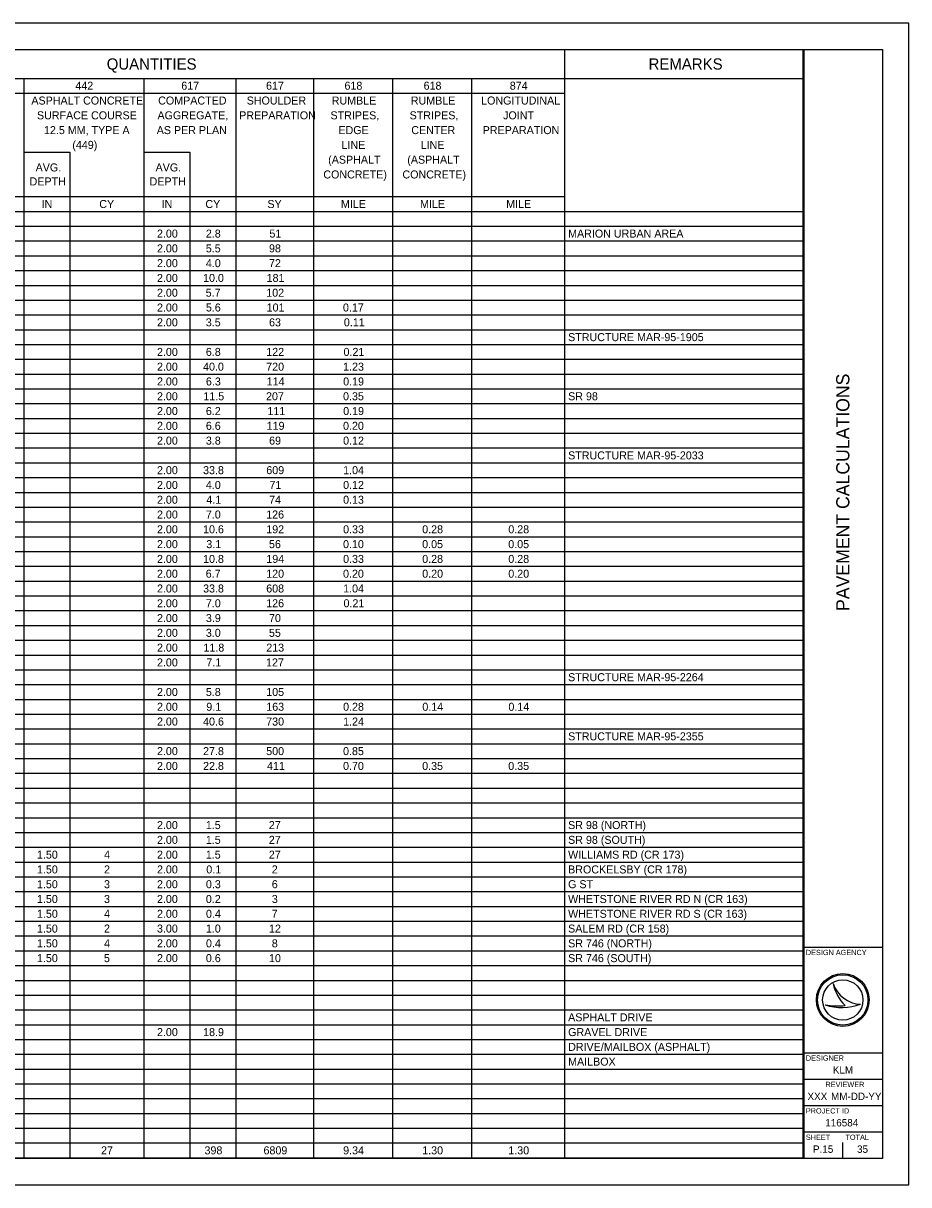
# Model space of a CAD drawing. Extents: x 0 to 34, y 0 to 22.
# Drawn here: x 17.22 to 34, y 0 to 22 of the extents above; entities that cross this region are included whole.
import ezdxf

# ---------------------------------------------------------------- set-up
doc = ezdxf.new("R2010")
doc.units = 0
for name, color, linetype in [('SH_Border', 7, 'Continuous'), ('SH_Cut_Line', 7, 'Continuous'), ('SH_Data', 7, 'Continuous'), ('SH_Text', 7, 'Continuous')]:
    doc.layers.add(name, color=color, linetype=linetype)

msp = doc.modelspace()

# ---------------------------------------------------------------- linework, layer by layer
at = {"layer": 'SH_Border'}
for p, q in [((32, 0.5), (32, 21.5)), ((32, 4.5), (33.5, 4.5)), ((32, 2.5), (33.5, 2.5)), ((32, 2), (33.5, 2)), ((32, 1.5), (33.5, 1.5)), ((32, 1), (33.5, 1))]:
    msp.add_line(p, q, dxfattribs=at)
msp.add_lwpolyline([(1.5, 21.5), (33.5, 21.5), (33.5, 0.5), (1.5, 0.5)], close=True, dxfattribs=at)
at = {"layer": 'SH_Cut_Line'}
msp.add_lwpolyline([(0, 0), (34, 0), (34, 22), (0, 22)], close=True, dxfattribs=at)
at = {"layer": 'SH_Data'}
for p, q in [((32.567, 3.81), (32.567, 3.81)), ((32.417, 3.41), (32.417, 3.41)), ((32.75, 3.5), (32.75, 3.5)), ((33.087, 3.419), (33.087, 3.419)), ((32.375, 0.675), (32.375, 0.675)), ((32.75, 0.5), (32.75, 0.8))]:
    msp.add_line(p, q, dxfattribs=at)
for radius in [0.5, 0.477, 0.477, 0.382]:
    msp.add_circle((32.75, 3.5), radius, dxfattribs=at)
for centre, radius, start, end in [((33.116, 3.998), 0.58, 198.9257, 198.9319), ((33.347, 3.97), 0.796, 191.6379, 191.6421), ((33.116, 3.998), 0.58, 198.9319, 267.1657), ((33.347, 3.97), 0.796, 191.6421, 226.0947), ((32.739, 4.37), 1.013, 251.4576, 290.0832), ((32.648, 4.654), 1.266, 259.4964, 259.4995), ((32.739, 4.37), 1.013, 251.4527, 251.4576), ((32.648, 4.654), 1.266, 259.4995, 276.6672)]:
    msp.add_arc(centre, radius, start, end, dxfattribs=at)
at = {"layer": 'SH_Text'}
for p, q in [((1.5, 21.5), (32.011, 21.5)), ((27.48, 21.5), (27.48, 0.512)), ((32.011, 21.5), (32.011, 0.512)), ((1.5, 20.956), (32.011, 20.956)), ((17.233, 20.956), (17.233, 0.512)), ((19.507, 20.956), (19.507, 0.512)), ((21.253, 20.956), (21.253, 0.512)), ((22.719, 20.956), (22.719, 0.512)), ((24.218, 20.956), (24.218, 0.512)), ((25.717, 20.956), (25.717, 0.512)), ((11.747, 20.676), (27.48, 20.676)), ((17.233, 19.556), (18.106, 19.556)), ((18.106, 19.556), (18.106, 0.512)), ((19.507, 19.556), (20.38, 19.556)), ((20.38, 19.556), (20.38, 0.512)), ((9.638, 18.716), (27.48, 18.716)), ((1.5, 18.436), (32.011, 18.436)), ((1.5, 18.156), (32.011, 18.156)), ((1.5, 17.876), (32.011, 17.876)), ((1.5, 17.596), (32.011, 17.596)), ((1.5, 17.315), (32.011, 17.315)), ((1.5, 17.035), (32.011, 17.035)), ((1.5, 16.755), (32.011, 16.755)), ((1.5, 16.475), (32.011, 16.475)), ((1.5, 16.195), (32.011, 16.195)), ((1.5, 15.915), (32.011, 15.915)), ((1.5, 15.635), (32.011, 15.635)), ((1.5, 15.355), (32.011, 15.355)), ((1.5, 15.075), (32.011, 15.075)), ((1.5, 14.795), (32.011, 14.795)), ((1.5, 14.515), (32.011, 14.515)), ((1.5, 14.235), (32.011, 14.235)), ((1.5, 13.955), (32.011, 13.955)), ((1.5, 13.675), (32.011, 13.675)), ((1.5, 13.395), (32.011, 13.395)), ((1.5, 13.114), (32.011, 13.114)), ((1.5, 12.834), (32.011, 12.834)), ((1.5, 12.554), (32.011, 12.554)), ((1.5, 12.274), (32.011, 12.274)), ((1.5, 11.994), (32.011, 11.994)), ((1.5, 11.714), (32.011, 11.714)), ((1.5, 11.434), (32.011, 11.434)), ((1.5, 11.154), (32.011, 11.154)), ((1.5, 10.874), (32.011, 10.874)), ((1.5, 10.594), (32.011, 10.594)), ((1.5, 10.314), (32.011, 10.314)), ((1.5, 10.034), (32.011, 10.034)), ((1.5, 9.754), (32.011, 9.754)), ((1.5, 9.474), (32.011, 9.474)), ((1.5, 9.194), (32.011, 9.194)), ((1.5, 8.914), (32.011, 8.914)), ((1.5, 8.633), (32.011, 8.633)), ((1.5, 8.353), (32.011, 8.353)), ((1.5, 8.073), (32.011, 8.073)), ((1.5, 7.793), (32.011, 7.793)), ((1.5, 7.513), (32.011, 7.513)), ((1.5, 7.233), (32.011, 7.233)), ((1.5, 6.953), (32.011, 6.953)), ((1.5, 6.673), (32.011, 6.673)), ((1.5, 6.393), (32.011, 6.393)), ((1.5, 6.113), (32.011, 6.113)), ((1.5, 5.833), (32.011, 5.833)), ((1.5, 5.553), (32.011, 5.553)), ((1.5, 5.273), (32.011, 5.273)), ((1.5, 4.993), (32.011, 4.993)), ((1.5, 4.713), (32.011, 4.713)), ((1.5, 4.432), (32.011, 4.432)), ((1.5, 4.152), (32.011, 4.152)), ((1.5, 3.872), (32.011, 3.872)), ((1.5, 3.592), (32.011, 3.592)), ((1.5, 3.312), (32.011, 3.312)), ((1.5, 3.032), (32.011, 3.032)), ((1.5, 2.752), (32.011, 2.752)), ((1.5, 2.472), (32.011, 2.472)), ((1.5, 2.192), (32.011, 2.192)), ((1.5, 1.912), (32.011, 1.912)), ((1.5, 1.632), (32.011, 1.632)), ((1.5, 1.352), (32.011, 1.352)), ((1.5, 1.072), (32.011, 1.072)), ((1.5, 0.792), (32.011, 0.792)), ((1.5, 0.512), (32.011, 0.512))]:
    msp.add_line(p, q, dxfattribs=at)

# ---------------------------------------------------------------- texts
at = {"layer": 'SH_Data'}
msp.add_text('PAVEMENT CALCULATIONS', height=0.25, rotation=90, dxfattribs=at).set_placement((32.875, 10.868))
for s, height, p in [('DESIGN AGENCY', 0.1, (32.05, 4.35)), ('DESIGNER', 0.1, (32.05, 2.35)), ('KLM', 0.14, (32.561, 2.105)), ('REVIEWER', 0.1, (32.422, 1.85)), ('XXX', 0.14, (32.081, 1.605)), ('MM-DD-YY', 0.14, (32.527, 1.605)), ('PROJECT ID', 0.1, (32.05, 1.35)), ('116584', 0.14, (32.418, 1.105)), ('SHEET', 0.1, (32.05, 0.85)), ('TOTAL', 0.1, (32.8, 0.85)), ('P.15', 0.14, (32.185, 0.605)), ('35', 0.14, (33.02, 0.605))]:
    msp.add_text(s, height=height, dxfattribs=at).set_placement(p)
at = {"layer": 'SH_Text'}
for s, height, p in [('QUANTITIES', 0.2122, (18.804, 21.122)), ('REMARKS', 0.2122, (29.07, 21.122)), ('442', 0.1516, (18.21, 20.741)), ('617', 0.1516, (20.217, 20.741)), ('617', 0.1516, (21.823, 20.741)), ('618', 0.1516, (23.309, 20.741)), ('618', 0.1516, (24.808, 20.741)), ('874', 0.1516, (26.441, 20.741)), ('ASPHALT CONCRETE', 0.15157, (17.377, 20.46)), ('COMPACTED', 0.1516, (19.779, 20.46)), ('SHOULDER', 0.1516, (21.456, 20.46)), ('RUMBLE', 0.1516, (23.067, 20.46)), ('RUMBLE', 0.1516, (24.566, 20.46)), ('LONGITUDINAL', 0.15157, (25.898, 20.46)), ('SURFACE COURSE', 0.15157, (17.483, 20.18)), ('AGGREGATE,', 0.1516, (19.766, 20.18)), ('PREPARATION', 0.15157, (21.314, 20.18)), ('STRIPES,', 0.1516, (23.044, 20.18)), ('STRIPES,', 0.1516, (24.543, 20.18)), ('JOINT', 0.1516, (26.314, 20.18)), ('12.5 MM, TYPE A', 0.15157, (17.616, 19.9)), ('AS PER PLAN', 0.15157, (19.752, 19.9)), ('EDGE', 0.1516, (23.194, 19.9)), ('CENTER', 0.1516, (24.575, 19.9)), ('PREPARATION', 0.15157, (25.927, 19.9)), ('(449)', 0.1516, (18.153, 19.62)), ('LINE', 0.1516, (23.253, 19.62)), ('LINE', 0.1516, (24.752, 19.62)), ('(ASPHALT', 0.1516, (23, 19.34)), ('(ASPHALT', 0.1516, (24.499, 19.34)), ('AVG. ', 0.1516, (17.457, 19.193)), ('AVG. ', 0.1516, (19.73, 19.193)), ('CONCRETE)', 0.1516, (22.908, 19.06)), ('CONCRETE)', 0.1516, (24.407, 19.06)), ('DEPTH', 0.1516, (17.343, 18.928)), ('DEPTH', 0.1516, (19.617, 18.928)), ('IN', 0.1516, (17.571, 18.5)), ('CY', 0.1516, (18.664, 18.5)), ('IN', 0.1516, (19.845, 18.5)), ('CY', 0.1516, (20.674, 18.5)), ('SY', 0.1516, (21.849, 18.5)), ('MILE', 0.1516, (23.242, 18.5)), ('MILE', 0.1516, (24.741, 18.5)), ('MILE', 0.1516, (26.372, 18.5)), ('2.00', 0.1516, (19.757, 17.94)), ('2.8', 0.1516, (20.683, 17.94)), ('51', 0.1516, (21.887, 17.94)), ('MARION URBAN AREA', 0.15157, (27.546, 17.94)), ('2.00', 0.1516, (19.757, 17.66)), ('5.5', 0.1516, (20.682, 17.66)), ('98', 0.1516, (21.879, 17.66)), ('2.00', 0.1516, (19.757, 17.38)), ('4.0', 0.1516, (20.683, 17.38)), ('72', 0.1516, (21.879, 17.38)), ('2.00', 0.1516, (19.757, 17.1)), ('10.0', 0.1516, (20.63, 17.1)), ('181', 0.1516, (21.834, 17.1)), ('2.00', 0.1516, (19.757, 16.82)), ('5.7', 0.1516, (20.68, 16.82)), ('102', 0.1516, (21.827, 16.82)), ('2.00', 0.1516, (19.757, 16.54)), ('5.6', 0.1516, (20.683, 16.54)), ('101', 0.1516, (21.834, 16.54)), ('0.17', 0.1516, (23.28, 16.54)), ('2.00', 0.1516, (19.757, 16.259)), ('3.5', 0.1516, (20.682, 16.259)), ('63', 0.1516, (21.88, 16.259)), ('0.11', 0.1516, (23.298, 16.259)), ('STRUCTURE MAR-95-1905', 0.15157, (27.546, 15.979)), ('2.00', 0.1516, (19.757, 15.699)), ('6.8', 0.1516, (20.683, 15.699)), ('122', 0.1516, (21.827, 15.699)), ('0.21', 0.1516, (23.291, 15.699)), ('2.00', 0.1516, (19.757, 15.419)), ('40.0', 0.1516, (20.63, 15.419)), ('720', 0.1516, (21.826, 15.419)), ('1.23', 0.1516, (23.283, 15.419)), ('2.00', 0.1516, (19.757, 15.139)), ('6.3', 0.1516, (20.684, 15.139)), ('114', 0.1516, (21.835, 15.139)), ('0.19', 0.1516, (23.284, 15.139)), ('2.00', 0.1516, (19.757, 14.859)), ('11.5', 0.1516, (20.636, 14.859)), ('207', 0.1516, (21.823, 14.859)), ('0.35', 0.1516, (23.282, 14.859)), ('SR 98', 0.1516, (27.546, 14.859)), ('2.00', 0.1516, (19.757, 14.579)), ('6.2', 0.1516, (20.683, 14.579)), ('111', 0.1516, (21.849, 14.579)), ('0.19', 0.1516, (23.284, 14.579)), ('2.00', 0.1516, (19.757, 14.299)), ('6.6', 0.1516, (20.683, 14.299)), ('119', 0.1516, (21.835, 14.299)), ('0.20', 0.1516, (23.282, 14.299)), ('2.00', 0.1516, (19.757, 14.019)), ('3.8', 0.1516, (20.683, 14.019)), ('69', 0.1516, (21.881, 14.019)), ('0.12', 0.1516, (23.283, 14.019)), ('STRUCTURE MAR-95-2033', 0.15157, (27.546, 13.739)), ('2.00', 0.1516, (19.757, 13.459)), ('33.8', 0.1516, (20.63, 13.459)), ('609', 0.1516, (21.828, 13.459)), ('1.04', 0.1516, (23.284, 13.459)), ('2.00', 0.1516, (19.757, 13.179)), ('4.0', 0.1516, (20.683, 13.179)), ('71', 0.1516, (21.887, 13.179)), ('0.12', 0.1516, (23.283, 13.179)), ('2.00', 0.1516, (19.757, 12.899)), ('4.1', 0.1516, (20.691, 12.899)), ('74', 0.1516, (21.881, 12.899)), ('0.13', 0.1516, (23.283, 12.899)), ('2.00', 0.1516, (19.757, 12.619)), ('7.0', 0.1516, (20.683, 12.619)), ('126', 0.1516, (21.826, 12.619)), ('2.00', 0.1516, (19.757, 12.339)), ('10.6', 0.1516, (20.63, 12.339)), ('192', 0.1516, (21.827, 12.339)), ('0.33', 0.1516, (23.283, 12.339)), ('0.28', 0.1516, (24.782, 12.339)), ('0.28', 0.1516, (26.413, 12.339)), ('2.00', 0.1516, (19.757, 12.058)), ('3.1', 0.1516, (20.691, 12.058)), ('56', 0.1516, (21.879, 12.058)), ('0.10', 0.1516, (23.282, 12.058)), ('0.05', 0.1516, (24.781, 12.058)), ('0.05', 0.1516, (26.412, 12.058)), ('2.00', 0.1516, (19.757, 11.778)), ('10.8', 0.1516, (20.63, 11.778)), ('194', 0.1516, (21.828, 11.778)), ('0.33', 0.1516, (23.283, 11.778)), ('0.28', 0.1516, (24.782, 11.778)), ('0.28', 0.1516, (26.413, 11.778)), ('2.00', 0.1516, (19.757, 11.498)), ('6.7', 0.1516, (20.68, 11.498)), ('120', 0.1516, (21.826, 11.498)), ('0.20', 0.1516, (23.282, 11.498)), ('0.20', 0.1516, (24.782, 11.498)), ('0.20', 0.1516, (26.413, 11.498)), ('2.00', 0.1516, (19.757, 11.218)), ('33.8', 0.1516, (20.63, 11.218)), ('608', 0.1516, (21.826, 11.218)), ('1.04', 0.1516, (23.284, 11.218)), ('2.00', 0.1516, (19.757, 10.938)), ('7.0', 0.1516, (20.683, 10.938)), ('126', 0.1516, (21.826, 10.938)), ('0.21', 0.1516, (23.291, 10.938)), ('2.00', 0.1516, (19.757, 10.658)), ('3.9', 0.1516, (20.684, 10.658)), ('70', 0.1516, (21.879, 10.658)), ('2.00', 0.1516, (19.757, 10.378)), ('3.0', 0.1516, (20.683, 10.378)), ('55', 0.1516, (21.878, 10.378)), ('2.00', 0.1516, (19.757, 10.098)), ('11.8', 0.1516, (20.637, 10.098)), ('213', 0.1516, (21.827, 10.098)), ('2.00', 0.1516, (19.757, 9.818)), ('7.1', 0.1516, (20.691, 9.818)), ('127', 0.1516, (21.823, 9.818)), ('STRUCTURE MAR-95-2264', 0.15157, (27.546, 9.538)), ('2.00', 0.1516, (19.757, 9.258)), ('5.8', 0.1516, (20.683, 9.258)), ('105', 0.1516, (21.826, 9.258)), ('2.00', 0.1516, (19.757, 8.978)), ('9.1', 0.1516, (20.691, 8.978)), ('163', 0.1516, (21.827, 8.978)), ('0.28', 0.1516, (23.283, 8.978)), ('0.14', 0.1516, (24.784, 8.978)), ('0.14', 0.1516, (26.415, 8.978)), ('2.00', 0.1516, (19.757, 8.698)), ('40.6', 0.1516, (20.63, 8.698)), ('730', 0.1516, (21.826, 8.698)), ('1.24', 0.1516, (23.284, 8.698)), ('STRUCTURE MAR-95-2355', 0.15157, (27.546, 8.418)), ('2.00', 0.1516, (19.757, 8.138)), ('27.8', 0.1516, (20.63, 8.138)), ('500', 0.1516, (21.826, 8.138)), ('0.85', 0.1516, (23.282, 8.138)), ('2.00', 0.1516, (19.757, 7.857)), ('22.8', 0.1516, (20.63, 7.857)), ('411', 0.1516, (21.841, 7.857)), ('0.70', 0.1516, (23.282, 7.857)), ('0.35', 0.1516, (24.781, 7.857)), ('0.35', 0.1516, (26.412, 7.857)), ('2.00', 0.1516, (19.757, 6.737)), ('1.5', 0.1516, (20.682, 6.737)), ('27', 0.1516, (21.876, 6.737)), ('SR 98 (NORTH)', 0.15157, (27.546, 6.737)), ('2.00', 0.1516, (19.757, 6.457)), ('1.5', 0.1516, (20.682, 6.457)), ('27', 0.1516, (21.876, 6.457)), ('SR 98 (SOUTH)', 0.15157, (27.546, 6.457)), ('1.50', 0.1516, (17.483, 6.177)), ('4', 0.152, (18.755, 6.177)), ('2.00', 0.1516, (19.757, 6.177)), ('1.5', 0.1516, (20.682, 6.177)), ('27', 0.1516, (21.876, 6.177)), ('WILLIAMS RD (CR 173)', 0.15157, (27.546, 6.177)), ('1.50', 0.1516, (17.483, 5.897)), ('2', 0.152, (18.753, 5.897)), ('2.00', 0.1516, (19.757, 5.897)), ('0.1', 0.1516, (20.691, 5.897)), ('2', 0.152, (21.932, 5.897)), ('BROCKELSBY (CR 178)', 0.15157, (27.546, 5.897)), ('1.50', 0.1516, (17.483, 5.617)), ('3', 0.152, (18.753, 5.617)), ('2.00', 0.1516, (19.757, 5.617)), ('0.3', 0.1516, (20.684, 5.617)), ('6', 0.152, (21.932, 5.617)), ('G ST', 0.1516, (27.546, 5.617)), ('1.50', 0.1516, (17.483, 5.337)), ('3', 0.152, (18.753, 5.337)), ('2.00', 0.1516, (19.757, 5.337)), ('0.2', 0.1516, (20.683, 5.337)), ('3', 0.152, (21.933, 5.337)), ('WHETSTONE RIVER RD N (CR 163)', 0.15157, (27.546, 5.337)), ('1.50', 0.1516, (17.483, 5.057)), ('4', 0.152, (18.755, 5.057)), ('2.00', 0.1516, (19.757, 5.057)), ('0.4', 0.1516, (20.685, 5.057)), ('7', 0.152, (21.929, 5.057)), ('WHETSTONE RIVER RD S (CR 163)', 0.15157, (27.546, 5.057)), ('1.50', 0.1516, (17.483, 4.777)), ('2', 0.152, (18.753, 4.777)), ('3.00', 0.1516, (19.757, 4.777)), ('1.0', 0.1516, (20.683, 4.777)), ('12', 0.1516, (21.879, 4.777)), ('SALEM RD (CR 158)', 0.15157, (27.546, 4.777)), ('1.50', 0.1516, (17.483, 4.497)), ('4', 0.152, (18.755, 4.497)), ('2.00', 0.1516, (19.757, 4.497)), ('0.4', 0.1516, (20.685, 4.497)), ('8', 0.152, (21.932, 4.497)), ('SR 746 (NORTH)', 0.15157, (27.546, 4.497)), ('1.50', 0.1516, (17.483, 4.217)), ('5', 0.152, (18.752, 4.217)), ('2.00', 0.1516, (19.757, 4.217)), ('0.6', 0.1516, (20.683, 4.217)), ('10', 0.1516, (21.879, 4.217)), ('SR 746 (SOUTH)', 0.15157, (27.546, 4.217)), ('ASPHALT DRIVE', 0.15157, (27.546, 3.096)), ('2.00', 0.1516, (19.757, 2.816)), ('18.9', 0.1516, (20.631, 2.816)), ('GRAVEL DRIVE', 0.15157, (27.546, 2.816)), ('DRIVE/MAILBOX (ASPHALT)', 0.15157, (27.546, 2.536)), ('MAILBOX', 0.1516, (27.546, 2.256)), ('27', 0.1516, (18.697, 0.576)), ('398', 0.1516, (20.657, 0.576)), ('6809', 0.1516, (21.775, 0.576)), ('9.34', 0.1516, (23.284, 0.576)), ('1.30', 0.1516, (24.782, 0.576)), ('1.30', 0.1516, (26.413, 0.576))]:
    msp.add_text(s, height=height, dxfattribs=at).set_placement(p)

doc.saveas('drawing.dxf')
